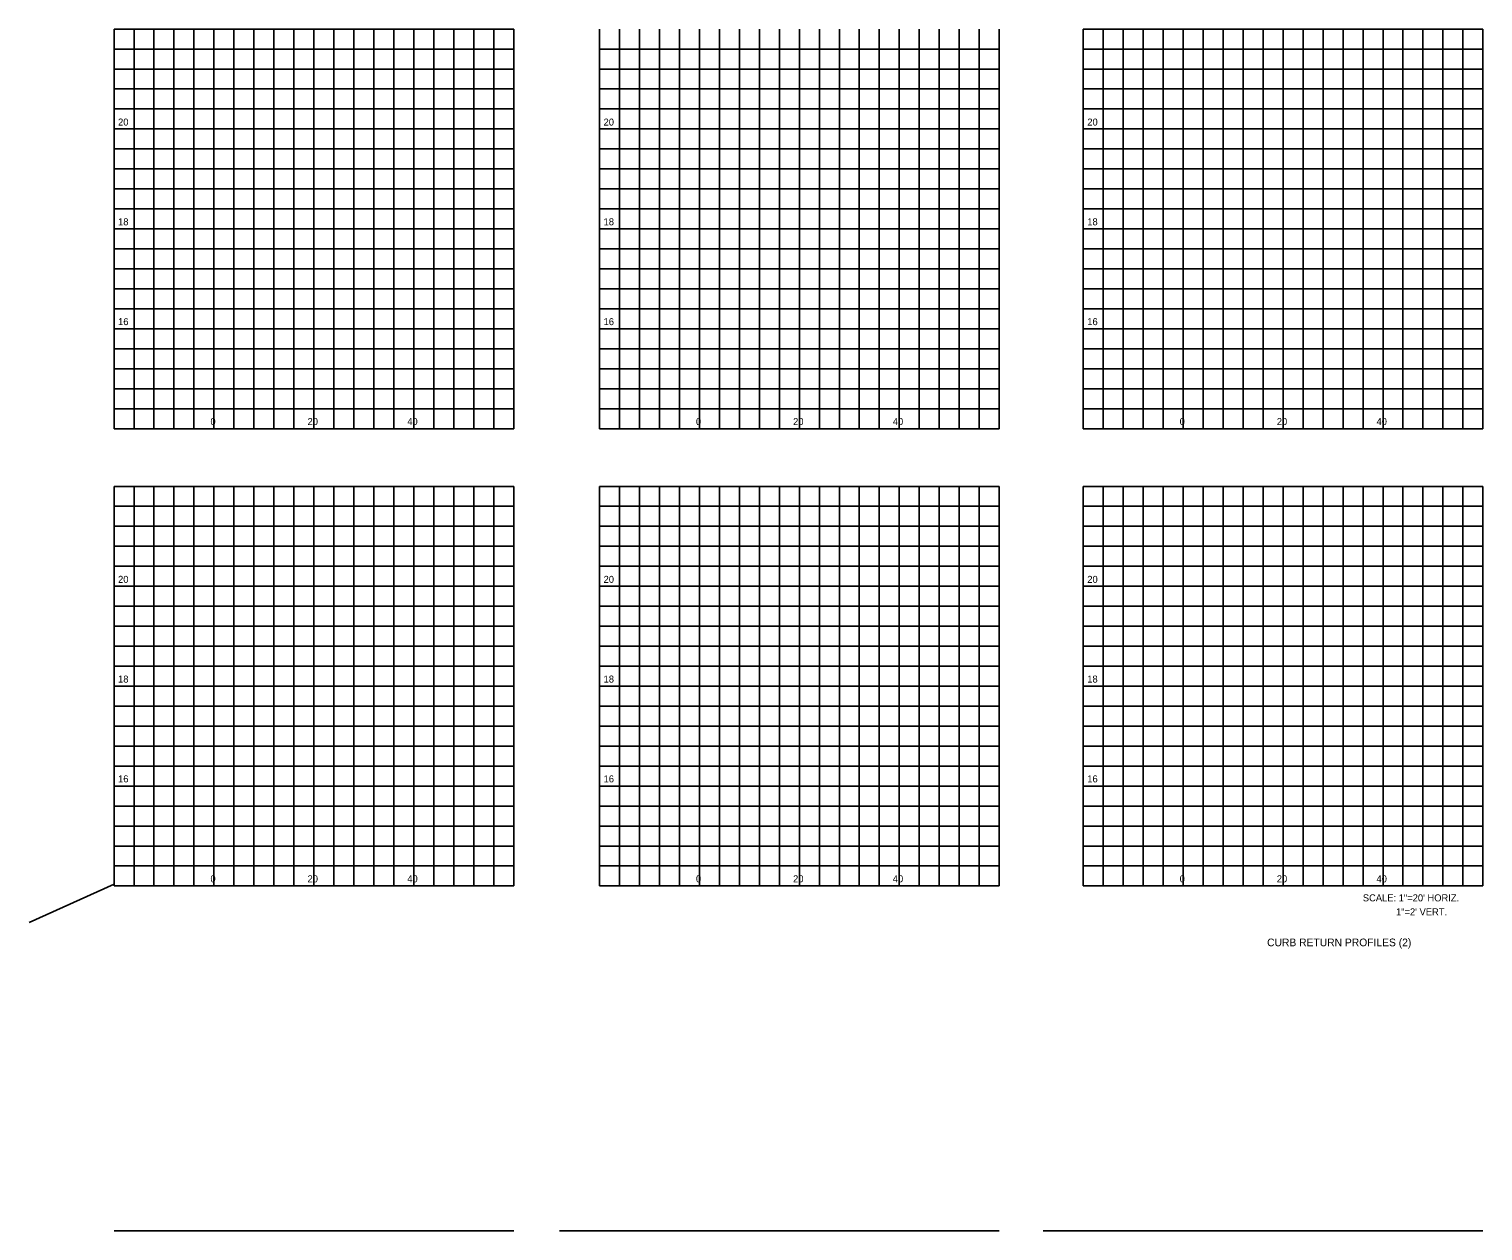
# Model space of a CAD drawing. Extents: x 127723 to 128378, y 21426 to 23736.
# Drawn here: x 127722.5 to 128013.5, y 23244.7 to 23485.3 of the extents above; entities that cross this region are included whole.
import ezdxf

# ---------------------------------------------------------------- set-up
doc = ezdxf.new("R2010")
doc.units = 0
for name, color, linetype in [('Default', 7, 'Continuous'), ('GroundCover', 7, 'Continuous'), ('Miscellaneous0', 7, 'Continuous'), ('SheetBorder_dp', 7, 'Continuous'), ('TextNotes', 7, 'Continuous')]:
    doc.layers.add(name, color=color, linetype=linetype)

msp = doc.modelspace()

# ---------------------------------------------------------------- linework, layer by layer
at = {"layer": 'Miscellaneous0'}
for p, q in [((127743.54, 23485.32), (127743.54, 23405.32)), ((127747.54, 23485.32), (127747.54, 23405.32)), ((127751.54, 23485.32), (127751.54, 23405.32)), ((127755.54, 23485.32), (127755.54, 23405.32)), ((127763.54, 23485.32), (127763.54, 23405.32)), ((127767.54, 23485.32), (127767.54, 23405.32)), ((127771.54, 23485.32), (127771.54, 23405.32)), ((127775.54, 23485.32), (127775.54, 23405.32)), ((127783.54, 23485.32), (127783.54, 23405.32)), ((127787.54, 23485.32), (127787.54, 23405.32)), ((127791.54, 23485.32), (127791.54, 23405.32)), ((127795.54, 23485.32), (127795.54, 23405.32)), ((127803.54, 23485.32), (127803.54, 23405.32)), ((127807.54, 23485.32), (127807.54, 23405.32)), ((127811.54, 23485.32), (127811.54, 23405.32)), ((127815.54, 23485.32), (127815.54, 23405.32)), ((127840.72, 23485.32), (127840.72, 23405.32)), ((127844.72, 23485.32), (127844.72, 23405.32)), ((127848.72, 23485.32), (127848.72, 23405.32)), ((127852.72, 23485.32), (127852.72, 23405.32)), ((127860.72, 23485.32), (127860.72, 23405.32)), ((127864.72, 23485.32), (127864.72, 23405.32)), ((127868.72, 23485.32), (127868.72, 23405.32)), ((127872.72, 23485.32), (127872.72, 23405.32)), ((127880.72, 23485.32), (127880.72, 23405.32)), ((127884.72, 23485.32), (127884.72, 23405.32)), ((127888.72, 23485.32), (127888.72, 23405.32)), ((127892.72, 23485.32), (127892.72, 23405.32)), ((127900.72, 23485.32), (127900.72, 23405.32)), ((127904.72, 23485.32), (127904.72, 23405.32)), ((127908.72, 23485.32), (127908.72, 23405.32)), ((127912.72, 23485.32), (127912.72, 23405.32)), ((127937.54, 23485.32), (127937.54, 23405.32)), ((127941.54, 23485.32), (127941.54, 23405.32)), ((127945.54, 23485.32), (127945.54, 23405.32)), ((127949.54, 23485.32), (127949.54, 23405.32)), ((127957.54, 23485.32), (127957.54, 23405.32)), ((127961.54, 23485.32), (127961.54, 23405.32)), ((127965.54, 23485.32), (127965.54, 23405.32)), ((127969.54, 23485.32), (127969.54, 23405.32)), ((127977.54, 23485.32), (127977.54, 23405.32)), ((127981.54, 23485.32), (127981.54, 23405.32)), ((127985.54, 23485.32), (127985.54, 23405.32)), ((127989.54, 23485.32), (127989.54, 23405.32)), ((127997.54, 23485.32), (127997.54, 23405.32)), ((128001.54, 23485.32), (128001.54, 23405.32)), ((128005.54, 23485.32), (128005.54, 23405.32)), ((128009.54, 23485.32), (128009.54, 23405.32)), ((127739.54, 23481.32), (127819.54, 23481.32)), ((127836.72, 23481.32), (127916.72, 23481.32)), ((127933.54, 23481.32), (128013.54, 23481.32)), ((127739.54, 23477.32), (127819.54, 23477.32)), ((127836.72, 23477.32), (127916.72, 23477.32)), ((127933.54, 23477.32), (128013.54, 23477.32)), ((127739.54, 23473.32), (127819.54, 23473.32)), ((127836.72, 23473.32), (127916.72, 23473.32)), ((127933.54, 23473.32), (128013.54, 23473.32)), ((127739.54, 23469.32), (127819.54, 23469.32)), ((127836.72, 23469.32), (127916.72, 23469.32)), ((127933.54, 23469.32), (128013.54, 23469.32)), ((127739.54, 23461.32), (127819.54, 23461.32)), ((127836.72, 23461.32), (127916.72, 23461.32)), ((127933.54, 23461.32), (128013.54, 23461.32)), ((127739.54, 23457.32), (127819.54, 23457.32)), ((127836.72, 23457.32), (127916.72, 23457.32)), ((127933.54, 23457.32), (128013.54, 23457.32)), ((127739.54, 23453.32), (127819.54, 23453.32)), ((127836.72, 23453.32), (127916.72, 23453.32)), ((127933.54, 23453.32), (128013.54, 23453.32)), ((127739.54, 23449.32), (127819.54, 23449.32)), ((127836.72, 23449.32), (127916.72, 23449.32)), ((127933.54, 23449.32), (128013.54, 23449.32)), ((127739.54, 23441.32), (127819.54, 23441.32)), ((127836.72, 23441.32), (127916.72, 23441.32)), ((127933.54, 23441.32), (128013.54, 23441.32)), ((127739.54, 23437.32), (127819.54, 23437.32)), ((127836.72, 23437.32), (127916.72, 23437.32)), ((127933.54, 23437.32), (128013.54, 23437.32)), ((127739.54, 23433.32), (127819.54, 23433.32)), ((127836.72, 23433.32), (127916.72, 23433.32)), ((127933.54, 23433.32), (128013.54, 23433.32)), ((127739.54, 23429.32), (127819.54, 23429.32)), ((127836.72, 23429.32), (127916.72, 23429.32)), ((127933.54, 23429.32), (128013.54, 23429.32)), ((127739.54, 23421.32), (127819.54, 23421.32)), ((127836.72, 23421.32), (127916.72, 23421.32)), ((127933.54, 23421.32), (128013.54, 23421.32)), ((127739.54, 23417.32), (127819.54, 23417.32)), ((127836.72, 23417.32), (127916.72, 23417.32)), ((127933.54, 23417.32), (128013.54, 23417.32)), ((127739.54, 23413.32), (127819.54, 23413.32)), ((127836.72, 23413.32), (127916.72, 23413.32)), ((127933.54, 23413.32), (128013.54, 23413.32)), ((127739.54, 23409.32), (127819.54, 23409.32)), ((127836.72, 23409.32), (127916.72, 23409.32)), ((127933.54, 23409.32), (128013.54, 23409.32)), ((127743.54, 23393.78), (127743.54, 23313.78)), ((127747.54, 23393.78), (127747.54, 23313.78)), ((127751.54, 23393.78), (127751.54, 23313.78)), ((127755.54, 23393.78), (127755.54, 23313.78)), ((127763.54, 23393.78), (127763.54, 23313.78)), ((127767.54, 23393.78), (127767.54, 23313.78)), ((127771.54, 23393.78), (127771.54, 23313.78)), ((127775.54, 23393.78), (127775.54, 23313.78)), ((127783.54, 23393.78), (127783.54, 23313.78)), ((127787.54, 23393.78), (127787.54, 23313.78)), ((127791.54, 23393.78), (127791.54, 23313.78)), ((127795.54, 23393.78), (127795.54, 23313.78)), ((127803.54, 23393.78), (127803.54, 23313.78)), ((127807.54, 23393.78), (127807.54, 23313.78)), ((127811.54, 23393.78), (127811.54, 23313.78)), ((127815.54, 23393.78), (127815.54, 23313.78)), ((127840.72, 23393.78), (127840.72, 23313.78)), ((127844.72, 23393.78), (127844.72, 23313.78)), ((127848.72, 23393.78), (127848.72, 23313.78)), ((127852.72, 23393.78), (127852.72, 23313.78)), ((127860.72, 23393.78), (127860.72, 23313.78)), ((127864.72, 23393.78), (127864.72, 23313.78)), ((127868.72, 23393.78), (127868.72, 23313.78)), ((127872.72, 23393.78), (127872.72, 23313.78)), ((127880.72, 23393.78), (127880.72, 23313.78)), ((127884.72, 23393.78), (127884.72, 23313.78)), ((127888.72, 23393.78), (127888.72, 23313.78)), ((127892.72, 23393.78), (127892.72, 23313.78)), ((127900.72, 23393.78), (127900.72, 23313.78)), ((127904.72, 23393.78), (127904.72, 23313.78)), ((127908.72, 23393.78), (127908.72, 23313.78)), ((127912.72, 23393.78), (127912.72, 23313.78)), ((127937.54, 23393.78), (127937.54, 23313.78)), ((127941.54, 23393.78), (127941.54, 23313.78)), ((127945.54, 23393.78), (127945.54, 23313.78)), ((127949.54, 23393.78), (127949.54, 23313.78)), ((127957.54, 23393.78), (127957.54, 23313.78)), ((127961.54, 23393.78), (127961.54, 23313.78)), ((127965.54, 23393.78), (127965.54, 23313.78)), ((127969.54, 23393.78), (127969.54, 23313.78)), ((127977.54, 23393.78), (127977.54, 23313.78)), ((127981.54, 23393.78), (127981.54, 23313.78)), ((127985.54, 23393.78), (127985.54, 23313.78)), ((127989.54, 23393.78), (127989.54, 23313.78)), ((127997.54, 23393.78), (127997.54, 23313.78)), ((128001.54, 23393.78), (128001.54, 23313.78)), ((128005.54, 23393.78), (128005.54, 23313.78)), ((128009.54, 23393.78), (128009.54, 23313.78)), ((127739.54, 23389.78), (127819.54, 23389.78)), ((127836.72, 23389.78), (127916.72, 23389.78)), ((127933.54, 23389.78), (128013.54, 23389.78)), ((127739.54, 23385.78), (127819.54, 23385.78)), ((127836.72, 23385.78), (127916.72, 23385.78)), ((127933.54, 23385.78), (128013.54, 23385.78)), ((127739.54, 23381.78), (127819.54, 23381.78)), ((127836.72, 23381.78), (127916.72, 23381.78)), ((127933.54, 23381.78), (128013.54, 23381.78)), ((127739.54, 23377.78), (127819.54, 23377.78)), ((127836.72, 23377.78), (127916.72, 23377.78)), ((127933.54, 23377.78), (128013.54, 23377.78)), ((127739.54, 23369.78), (127819.54, 23369.78)), ((127836.72, 23369.78), (127916.72, 23369.78)), ((127933.54, 23369.78), (128013.54, 23369.78)), ((127739.54, 23365.78), (127819.54, 23365.78)), ((127836.72, 23365.78), (127916.72, 23365.78)), ((127933.54, 23365.78), (128013.54, 23365.78)), ((127739.54, 23361.78), (127819.54, 23361.78)), ((127836.72, 23361.78), (127916.72, 23361.78)), ((127933.54, 23361.78), (128013.54, 23361.78)), ((127739.54, 23357.78), (127819.54, 23357.78)), ((127836.72, 23357.78), (127916.72, 23357.78)), ((127933.54, 23357.78), (128013.54, 23357.78)), ((127739.54, 23349.78), (127819.54, 23349.78)), ((127836.72, 23349.78), (127916.72, 23349.78)), ((127933.54, 23349.78), (128013.54, 23349.78)), ((127739.54, 23345.78), (127819.54, 23345.78)), ((127836.72, 23345.78), (127916.72, 23345.78)), ((127933.54, 23345.78), (128013.54, 23345.78)), ((127739.54, 23341.78), (127819.54, 23341.78)), ((127836.72, 23341.78), (127916.72, 23341.78)), ((127933.54, 23341.78), (128013.54, 23341.78)), ((127739.54, 23337.78), (127819.54, 23337.78)), ((127836.72, 23337.78), (127916.72, 23337.78)), ((127933.54, 23337.78), (128013.54, 23337.78)), ((127739.54, 23329.78), (127819.54, 23329.78)), ((127836.72, 23329.78), (127916.72, 23329.78)), ((127933.54, 23329.78), (128013.54, 23329.78)), ((127739.54, 23325.78), (127819.54, 23325.78)), ((127836.72, 23325.78), (127916.72, 23325.78)), ((127933.54, 23325.78), (128013.54, 23325.78)), ((127739.54, 23321.78), (127819.54, 23321.78)), ((127836.72, 23321.78), (127916.72, 23321.78)), ((127933.54, 23321.78), (128013.54, 23321.78)), ((127739.54, 23317.78), (127819.54, 23317.78)), ((127836.72, 23317.78), (127916.72, 23317.78)), ((127933.54, 23317.78), (128013.54, 23317.78))]:
    msp.add_line(p, q, dxfattribs=at)
at = {"layer": 'SheetBorder_dp'}
for p, q in [((127739.54, 23485.32), (127819.54, 23485.32)), ((127739.54, 23485.32), (127739.54, 23405.32)), ((127759.54, 23485.32), (127759.54, 23425.32)), ((127759.54, 23485.32), (127759.54, 23405.32)), ((127779.54, 23485.32), (127779.54, 23405.32)), ((127799.54, 23485.32), (127799.54, 23405.32)), ((127819.54, 23485.32), (127819.54, 23405.32)), ((127836.72, 23485.32), (127836.72, 23405.32)), ((127856.72, 23485.32), (127856.72, 23425.32)), ((127856.72, 23485.32), (127856.72, 23405.32)), ((127876.72, 23485.32), (127876.72, 23405.32)), ((127896.72, 23485.32), (127896.72, 23405.32)), ((127916.72, 23485.32), (127916.72, 23405.32)), ((127933.54, 23485.32), (128013.54, 23485.32)), ((127933.54, 23485.32), (127933.54, 23405.32)), ((127953.54, 23485.32), (127953.54, 23425.32)), ((127953.54, 23485.32), (127953.54, 23405.32)), ((127973.54, 23485.32), (127973.54, 23405.32)), ((127993.54, 23485.32), (127993.54, 23405.32)), ((128013.54, 23485.32), (128013.54, 23405.32)), ((127739.54, 23465.32), (127819.54, 23465.32)), ((127836.72, 23465.32), (127916.72, 23465.32)), ((127933.54, 23465.32), (128013.54, 23465.32)), ((127739.54, 23445.32), (127819.54, 23445.32)), ((127836.72, 23445.32), (127916.72, 23445.32)), ((127933.54, 23445.32), (128013.54, 23445.32)), ((127739.54, 23425.32), (127819.54, 23425.32)), ((127739.54, 23425.32), (127819.54, 23425.32)), ((127836.72, 23425.32), (127916.72, 23425.32)), ((127836.72, 23425.32), (127916.72, 23425.32)), ((127933.54, 23425.32), (128013.54, 23425.32)), ((127933.54, 23425.32), (128013.54, 23425.32)), ((127739.54, 23405.32), (127819.54, 23405.32)), ((127836.72, 23405.32), (127916.72, 23405.32)), ((127933.54, 23405.32), (128013.54, 23405.32)), ((127739.54, 23393.78), (127819.54, 23393.78)), ((127739.54, 23393.78), (127739.54, 23313.78)), ((127759.54, 23393.78), (127759.54, 23333.78)), ((127759.54, 23393.78), (127759.54, 23313.78)), ((127779.54, 23393.78), (127779.54, 23313.78)), ((127799.54, 23393.78), (127799.54, 23313.78)), ((127819.54, 23393.78), (127819.54, 23313.78)), ((127836.72, 23393.78), (127916.72, 23393.78)), ((127836.72, 23393.78), (127836.72, 23313.78)), ((127856.72, 23393.78), (127856.72, 23333.78)), ((127856.72, 23393.78), (127856.72, 23313.78)), ((127876.72, 23393.78), (127876.72, 23313.78)), ((127896.72, 23393.78), (127896.72, 23313.78)), ((127916.72, 23393.78), (127916.72, 23313.78)), ((127933.54, 23393.78), (128013.54, 23393.78)), ((127933.54, 23393.78), (127933.54, 23313.78)), ((127953.54, 23393.78), (127953.54, 23333.78)), ((127953.54, 23393.78), (127953.54, 23313.78)), ((127973.54, 23393.78), (127973.54, 23313.78)), ((127993.54, 23393.78), (127993.54, 23313.78)), ((128013.54, 23393.78), (128013.54, 23313.78)), ((127739.54, 23373.78), (127819.54, 23373.78)), ((127836.72, 23373.78), (127916.72, 23373.78)), ((127933.54, 23373.78), (128013.54, 23373.78)), ((127739.54, 23353.78), (127819.54, 23353.78)), ((127836.72, 23353.78), (127916.72, 23353.78)), ((127933.54, 23353.78), (128013.54, 23353.78)), ((127739.54, 23333.78), (127819.54, 23333.78)), ((127739.54, 23333.78), (127819.54, 23333.78)), ((127836.72, 23333.78), (127916.72, 23333.78)), ((127836.72, 23333.78), (127916.72, 23333.78)), ((127933.54, 23333.78), (128013.54, 23333.78)), ((127933.54, 23333.78), (128013.54, 23333.78)), ((127739.54, 23313.78), (127819.54, 23313.78)), ((127836.72, 23313.78), (127916.72, 23313.78)), ((127933.54, 23313.78), (128013.54, 23313.78)), ((127739.54, 23244.73), (127819.54, 23244.73)), ((127828.72, 23244.73), (127916.72, 23244.73)), ((127925.54, 23244.73), (128013.54, 23244.73))]:
    msp.add_line(p, q, dxfattribs=at)
at = {"layer": 'TextNotes'}
msp.add_line((127739.54, 23314.15), (127722.54, 23306.49), dxfattribs=at)

# ---------------------------------------------------------------- texts
at = {"layer": 'Default'}
msp.add_text('CURB RETURN PROFILES (2)', height=1.5418, dxfattribs=at).set_placement((127970.34, 23301.71))
at = {"layer": 'GroundCover'}
for s, p in [('20', (127740.35, 23466)), ('20', (127837.53, 23466)), ('20', (127934.35, 23466)), ('18', (127740.35, 23446.04)), ('18', (127837.53, 23446.04)), ('18', (127934.35, 23446.04)), ('16', (127740.35, 23426.05)), ('16', (127837.53, 23426.05)), ('16', (127934.35, 23426.05)), ('0', (127758.84, 23406.05)), ('20', (127778.28, 23406.05)), ('40', (127798.24, 23406.05)), ('0', (127856.02, 23406.05)), ('20', (127875.46, 23406.05)), ('40', (127895.42, 23406.05)), ('0', (127952.84, 23406.05)), ('20', (127972.28, 23406.05)), ('40', (127992.24, 23406.05)), ('20', (127740.35, 23374.46)), ('20', (127837.53, 23374.46)), ('20', (127934.35, 23374.46)), ('18', (127740.35, 23354.5)), ('18', (127837.53, 23354.5)), ('18', (127934.35, 23354.5)), ('16', (127740.35, 23334.52)), ('16', (127837.53, 23334.52)), ('16', (127934.35, 23334.52)), ('0', (127758.84, 23314.52)), ('20', (127778.28, 23314.52)), ('40', (127798.24, 23314.52)), ('0', (127856.02, 23314.52)), ('20', (127875.46, 23314.52)), ('40', (127895.42, 23314.52)), ('0', (127952.84, 23314.52)), ('20', (127972.28, 23314.52)), ('40', (127992.24, 23314.52)), ('SCALE: 1"=20\' HORIZ.', (127989.5, 23310.7)), ('  1"=2\' VERT.', (127995.1, 23307.9))]:
    msp.add_text(s, height=1.4, dxfattribs=at).set_placement(p)

doc.saveas('drawing.dxf')
